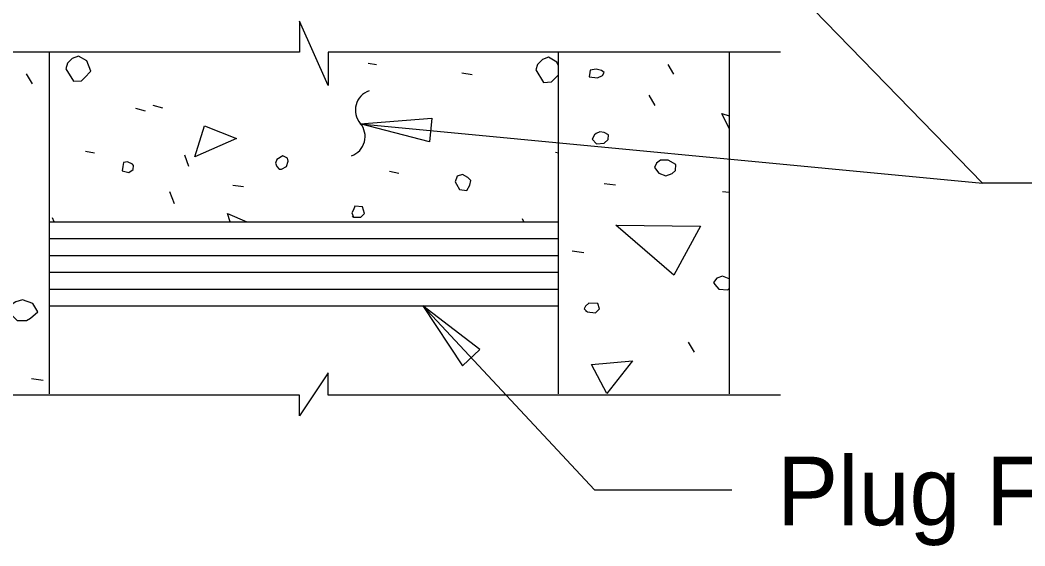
# Model space of a CAD drawing. Extents: x 112310.1 to 112345.4, y 111943.5 to 111959.3.
# Drawn here: x 112320.099 to 112321.577, y 111948.183 to 111948.957 of the extents above; entities that cross this region are included whole.
import ezdxf

# ---------------------------------------------------------------- set-up
doc = ezdxf.new("R2010")
doc.units = 0
for name, color, linetype in [('Dimension', 7, 'Continuous'), ('Miscellaneous', 7, 'Continuous'), ('PileConc', 7, 'Continuous'), ('TextStructures', 7, 'Continuous')]:
    doc.layers.add(name, color=color, linetype=linetype)

msp = doc.modelspace()

# ---------------------------------------------------------------- linework, layer by layer
at = {"layer": 'Dimension'}
for p, q in [((112321.5142, 111948.7166), (112320.6427, 111949.6138)), ((112320.5992, 111948.8042), (112321.5142, 111948.7165)), ((112321.6062, 111948.7165), (112321.5142, 111948.7165)), ((112320.4649, 111948.4049), (112319.8331, 111948.4049)), ((112320.5302, 111948.4049), (112320.5302, 111948.4049)), ((112321.217, 111948.4049), (112320.5969, 111948.4049))]:
    msp.add_line(p, q, dxfattribs=at)
for points in [[(112321.217, 111948.9094), (112320.5519, 111948.9094), (112320.5519, 111948.8604), (112320.5099, 111948.9551), (112320.5099, 111948.9094), (112319.8331, 111948.9094)], [(112320.6913, 111948.5364), (112320.9439, 111948.2655), (112321.1454, 111948.2655)], [(112320.5969, 111948.4049), (112320.5519, 111948.4049), (112320.5519, 111948.4375), (112320.5099, 111948.3744), (112320.5099, 111948.4049), (112320.4649, 111948.4049)]]:
    msp.add_lwpolyline(points, dxfattribs=at)
for points in [[(112320.5992, 111948.8042), (112320.7045, 111948.8125), (112320.7013, 111948.7773)], [(112320.6913, 111948.5364), (112320.7494, 111948.4482), (112320.7752, 111948.4722)]]:
    msp.add_lwpolyline(points, close=True, dxfattribs=at)
for centre, start, end in [((112320.6219, 111948.8241), 108.9534, 220.6806), ((112320.5767, 111948.7853), 288.9534, 40.6806)]:
    msp.add_arc(centre, 0.0298, start, end, dxfattribs=at)
at = {"layer": 'Miscellaneous'}
for p, q in [((112320.6108, 111948.8931), (112320.6232, 111948.8913)), ((112321.0603, 111948.877), (112321.0519, 111948.8914)), ((112320.1175, 111948.8629), (112320.1086, 111948.8777)), ((112320.7487, 111948.8789), (112320.7637, 111948.8763)), ((112321.0327, 111948.8311), (112321.0243, 111948.8463)), ((112320.2944, 111948.8312), (112320.3085, 111948.8277)), ((112320.2687, 111948.8268), (112320.2829, 111948.8232)), ((112320.1954, 111948.764), (112320.2086, 111948.7614)), ((112320.3474, 111948.741), (112320.3412, 111948.7578)), ((112320.8866, 111948.7622), (112320.8907, 111948.7614)), ((112320.6425, 111948.7342), (112320.6558, 111948.7315)), ((112320.4119, 111948.7136), (112320.4278, 111948.7119)), ((112320.9578, 111948.7164), (112320.9744, 111948.7141)), ((112320.3262, 111948.6862), (112320.3191, 111948.7039)), ((112321.1318, 111948.7046), (112321.1415, 111948.7033)), ((112320.1492, 111948.6597), (112320.1468, 111948.6659)), ((112320.1422, 111948.6597), (112320.8907, 111948.6597)), ((112320.8397, 111948.6597), (112320.838, 111948.6641)), ((112320.1422, 111948.6351), (112320.8907, 111948.6351)), ((112320.1422, 111948.6104), (112320.8907, 111948.6104)), ((112320.9107, 111948.617), (112320.9278, 111948.6145)), ((112320.1422, 111948.5857), (112320.8907, 111948.5857)), ((112320.1422, 111948.561), (112320.8907, 111948.561)), ((112320.1422, 111948.5364), (112320.8907, 111948.5364)), ((112321.0908, 111948.4681), (112321.0819, 111948.4829)), ((112320.1161, 111948.4293), (112320.1329, 111948.4269))]:
    msp.add_line(p, q, dxfattribs=at)
for points in [[(112320.1662, 111948.8851), (112320.1777, 111948.8665), (112320.1892, 111948.8674), (112320.1936, 111948.8718), (112320.2033, 111948.8816), (112320.1971, 111948.8966), (112320.1848, 111948.9037), (112320.1759, 111948.9001), (112320.1689, 111948.8931), (112320.1662, 111948.8851)], [(112320.8907, 111948.8891), (112320.8883, 111948.8948), (112320.876, 111948.9019), (112320.8671, 111948.8984), (112320.8601, 111948.8913), (112320.8574, 111948.8833)], [(112320.8574, 111948.8833), (112320.8689, 111948.8648), (112320.8804, 111948.8657), (112320.8848, 111948.8701), (112320.8907, 111948.876)], [(112320.9357, 111948.873), (112320.9482, 111948.8718), (112320.9556, 111948.8751), (112320.9578, 111948.8796), (112320.954, 111948.8822), (112320.9461, 111948.8844), (112320.9372, 111948.8829), (112320.9367, 111948.8795), (112320.9357, 111948.873)], [(112321.1415, 111948.7973), (112321.1307, 111948.8191), (112321.1415, 111948.8159)], [(112320.3562, 111948.7552), (112320.3704, 111948.8011), (112320.4172, 111948.7826), (112320.3562, 111948.7552)], [(112320.9402, 111948.7814), (112320.9467, 111948.7747), (112320.9578, 111948.7754), (112320.964, 111948.7809), (112320.9645, 111948.788), (112320.9578, 111948.791), (112320.9517, 111948.7921), (112320.9463, 111948.7898), (112320.9435, 111948.788), (112320.9402, 111948.7814)], [(112320.48, 111948.7375), (112320.4835, 111948.7375), (112320.4906, 111948.741), (112320.4932, 111948.749), (112320.4924, 111948.7534), (112320.4853, 111948.7569), (112320.4764, 111948.7516), (112320.4747, 111948.7463), (112320.4764, 111948.741), (112320.48, 111948.7375)], [(112320.2493, 111948.7348), (112320.259, 111948.7322), (112320.2652, 111948.7366), (112320.2661, 111948.7428), (112320.2643, 111948.7446), (112320.2572, 111948.7481), (112320.2511, 111948.7472), (112320.2502, 111948.741), (112320.2493, 111948.7348)], [(112321.032, 111948.7399), (112321.0381, 111948.7315), (112321.0487, 111948.7274), (112321.058, 111948.7308), (112321.063, 111948.7355), (112321.0635, 111948.744), (112321.052, 111948.7503), (112321.0409, 111948.7503), (112321.0348, 111948.7463), (112321.032, 111948.7399)], [(112320.7407, 111948.7154), (112320.7451, 111948.7074), (112320.7558, 111948.7057), (112320.7602, 111948.7136), (112320.7619, 111948.7207), (112320.7575, 111948.7251), (112320.7496, 111948.7295), (112320.7416, 111948.7269), (112320.739, 111948.7189), (112320.7407, 111948.7154)], [(112320.5896, 111948.6668), (112320.6002, 111948.6668), (112320.6055, 111948.6721), (112320.6028, 111948.6818), (112320.5914, 111948.6827), (112320.5896, 111948.6774), (112320.5869, 111948.673), (112320.5896, 111948.6668), (112320.5878, 111948.6686)], [(112320.408, 111948.6597), (112320.404, 111948.6721), (112320.4323, 111948.6597)], [(112321.0603, 111948.5816), (112320.9749, 111948.6547), (112321.0997, 111948.6536), (112321.0603, 111948.5816)], [(112321.1415, 111948.576), (112321.1318, 111948.5797), (112321.1234, 111948.5771), (112321.1185, 111948.5708), (112321.1208, 111948.5679)], [(112321.1208, 111948.5679), (112321.1267, 111948.5609), (112321.1396, 111948.5598), (112321.1415, 111948.562)], [(112320.0796, 111948.5296), (112320.0946, 111948.5145), (112320.1084, 111948.5149), (112320.1145, 111948.5182), (112320.1252, 111948.5274), (112320.1179, 111948.5395), (112320.1029, 111948.5451), (112320.0929, 111948.5422), (112320.0845, 111948.5366), (112320.0796, 111948.5296)], [(112320.9329, 111948.5276), (112320.9451, 111948.5262), (112320.9512, 111948.5317), (112320.9484, 111948.5395), (112320.9352, 111948.5403), (112320.9306, 111948.5358), (112320.9285, 111948.5321), (112320.9329, 111948.5276), (112320.9306, 111948.5291)], [(112320.9617, 111948.4072), (112320.9395, 111948.4501), (112320.9994, 111948.4554), (112320.9617, 111948.4072)]]:
    msp.add_lwpolyline(points, dxfattribs=at)
at = {"layer": 'PileConc'}
for p, q in [((112320.1422, 111948.4069), (112320.1422, 111948.9094)), ((112320.8907, 111948.4069), (112320.8907, 111948.9094)), ((112321.1415, 111948.9094), (112321.1415, 111948.4069))]:
    msp.add_line(p, q, dxfattribs=at)

# ---------------------------------------------------------------- texts
at = {"layer": 'TextStructures'}
msp.add_text('Plug Form', height=0.1008, dxfattribs=at).set_placement((112321.2121, 111948.2136))

doc.saveas('drawing.dxf')
